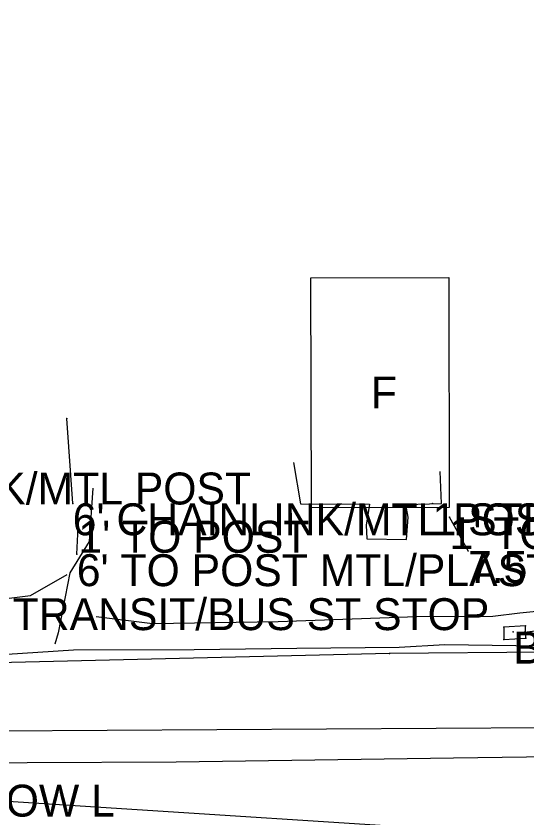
# Model space of a CAD drawing. Extents: x 1304270 to 1306561, y 1876019 to 1876752.
# Drawn here: x 1305816.1 to 1305896.1, y 1876400.4 to 1876526.1 of the extents above; entities that cross this region are included whole.
import ezdxf

# ---------------------------------------------------------------- set-up
doc = ezdxf.new("R2010")
doc.units = 0
for name, color, linetype in [('Default', 7, 'Continuous'), ('S_BUILDING', 7, 'Continuous'), ('S_BUILDING_ANNOT', 7, 'Continuous'), ('S_CROSS_DRAIN', 7, 'Continuous'), ('S_DRG_PT_SYM', 7, 'Continuous'), ('S_DROP_INLET', 7, 'Continuous'), ('S_EDGE_PAVEMENT', 7, 'Continuous'), ('S_ELECTRIC_UTILITIES_ANNOT', 7, 'Continuous'), ('S_FENCE', 7, 'Continuous'), ('S_FENCE_ANNOT', 7, 'Continuous'), ('S_MANHOLE_ANNOT', 7, 'Continuous'), ('S_MISC_STRUCTURES_ANNOT', 7, 'Continuous'), ('S_MSC_PT_SYM', 7, 'Continuous'), ('S_PARKING', 7, 'Continuous'), ('S_PAVEMENT_CROWN', 7, 'Continuous'), ('S_SANITARY_SEWER', 7, 'Continuous'), ('S_SHOULDER', 7, 'Continuous'), ('S_SIGN', 7, 'Continuous'), ('S_SIGN_ANNOT', 7, 'Continuous'), ('S_STR_PT_SYM', 7, 'Continuous'), ('S_UTL_PT_SYM', 7, 'Continuous'), ('S_WATER_UTILITIES', 7, 'Continuous')]:
    doc.layers.add(name, color=color, linetype=linetype)

msp = doc.modelspace()

# ---------------------------------------------------------------- linework, layer by layer
at = {"layer": 'Default'}
msp.add_line((1305473.53, 1876424.94), (1305993.25, 1876391.55), dxfattribs=at)
at = {"layer": 'S_BUILDING'}
msp.add_lwpolyline([(1305883.85, 1876485.1), (1305883.93, 1876449.06), (1305862.33, 1876449.01), (1305862.25, 1876485.05)], close=True, dxfattribs=at)
at = {"layer": 'S_CROSS_DRAIN'}
msp.add_line((1305895.71, 1876429.5), (1305904.32, 1876430.63), dxfattribs=at)
at = {"layer": 'S_DRG_PT_SYM'}
for points in [[(1305892.49, 1876430.27), (1305892.49, 1876430.32), (1305892.49, 1876430.27), (1305892.44, 1876430.27), (1305892.49, 1876430.27), (1305892.49, 1876430.22), (1305892.49, 1876430.27), (1305892.54, 1876430.27)], [(1305895.71, 1876429.5), (1305895.71, 1876429.55), (1305895.71, 1876429.5), (1305895.66, 1876429.5), (1305895.71, 1876429.5), (1305895.71, 1876429.45), (1305895.71, 1876429.5), (1305895.76, 1876429.5)], [(1305895.85, 1876430.5), (1305895.85, 1876430.55), (1305895.85, 1876430.5), (1305895.8, 1876430.5), (1305895.85, 1876430.5), (1305895.85, 1876430.45), (1305895.85, 1876430.5), (1305895.9, 1876430.5)], [(1305892.45, 1876428.38), (1305892.45, 1876428.43), (1305892.45, 1876428.38), (1305892.4, 1876428.38), (1305892.45, 1876428.38), (1305892.45, 1876428.33), (1305892.45, 1876428.38), (1305892.5, 1876428.38)], [(1305895.93, 1876428.55), (1305895.93, 1876428.6), (1305895.93, 1876428.55), (1305895.88, 1876428.55), (1305895.93, 1876428.55), (1305895.93, 1876428.5), (1305895.93, 1876428.55), (1305895.98, 1876428.55)]]:
    msp.add_lwpolyline(points, dxfattribs=at)
at = {"layer": 'S_DROP_INLET'}
for p, q in [((1305892.49, 1876430.27), (1305892.45, 1876428.38)), ((1305895.85, 1876430.5), (1305892.49, 1876430.27)), ((1305895.93, 1876428.55), (1305895.85, 1876430.5)), ((1305892.45, 1876428.38), (1305895.93, 1876428.55))]:
    msp.add_line(p, q, dxfattribs=at)
at = {"layer": 'S_EDGE_PAVEMENT'}
msp.add_lwpolyline([(1305650.55, 1876423.21), (1305674.32, 1876423.35), (1305698.09, 1876423.48), (1305721.97, 1876423.8), (1305745.85, 1876424.12), (1305770.29, 1876424.67), (1305794.74, 1876425.23), (1305811.42, 1876425.85), (1305825.07, 1876426.72), (1305843.96, 1876426.78), (1305860.03, 1876426.98), (1305876.09, 1876427.18), (1305883.24, 1876427.59), (1305898.06, 1876427.36), (1305904.05, 1876427.05), (1305918.23, 1876426.76), (1305933.32, 1876426.78)], dxfattribs=at)
at = {"layer": 'S_FENCE'}
msp.add_line((1305824.93, 1876449.69), (1305824, 1876463.01), dxfattribs=at)
msp.add_lwpolyline([(1305824.93, 1876449.69), (1305824, 1876463.01)], dxfattribs=at)
msp.add_lwpolyline([(1305824.93, 1876449.69), (1305824, 1876463.01)], dxfattribs=at)
at = {"layer": 'S_MSC_PT_SYM'}
for points in [[(1305824, 1876463.01), (1305824, 1876463.06), (1305824, 1876463.01), (1305823.95, 1876463.01), (1305824, 1876463.01), (1305824, 1876462.96), (1305824, 1876463.01), (1305824.05, 1876463.01)], [(1305824.93, 1876449.69), (1305824.93, 1876449.74), (1305824.93, 1876449.69), (1305824.88, 1876449.69), (1305824.93, 1876449.69), (1305824.93, 1876449.64), (1305824.93, 1876449.69), (1305824.98, 1876449.69)], [(1305883.97, 1876447.52), (1305883.97, 1876447.57), (1305883.97, 1876447.52), (1305883.92, 1876447.52), (1305883.97, 1876447.52), (1305883.97, 1876447.47), (1305883.97, 1876447.52), (1305884.02, 1876447.52)], [(1305825.82, 1876446.96), (1305825.82, 1876447.01), (1305825.82, 1876446.96), (1305825.77, 1876446.96), (1305825.82, 1876446.96), (1305825.82, 1876446.91), (1305825.82, 1876446.96), (1305825.87, 1876446.96)], [(1305886.87, 1876442.23), (1305886.87, 1876442.28), (1305886.87, 1876442.23), (1305886.82, 1876442.23), (1305886.87, 1876442.23), (1305886.87, 1876442.18), (1305886.87, 1876442.23), (1305886.92, 1876442.23)], [(1305825.57, 1876441.72), (1305825.57, 1876441.77), (1305825.57, 1876441.72), (1305825.52, 1876441.72), (1305825.57, 1876441.72), (1305825.57, 1876441.67), (1305825.57, 1876441.72), (1305825.62, 1876441.72)]]:
    msp.add_lwpolyline(points, dxfattribs=at)
at = {"layer": 'S_PARKING'}
for points in [[(1305901.16, 1876526.05), (1305901.3, 1876519.98), (1305901.45, 1876495.85), (1305901.48, 1876479.31), (1305901.6, 1876457.42), (1305900.96, 1876445.11), (1305900.93, 1876443.49), (1305900.91, 1876441.84), (1305902.67, 1876441.64), (1305902.25, 1876438.69), (1305899.45, 1876436.19), (1305899.74, 1876432.97), (1305894.96, 1876432.47), (1305890.73, 1876431.98), (1305878.86, 1876431.91), (1305857.12, 1876431.13), (1305837.44, 1876430.83), (1305828.63, 1876431.93)], [(1305859.5, 1876456.1), (1305860.61, 1876449.63), (1305871.42, 1876449.58), (1305870.93, 1876446.28), (1305871.01, 1876444.12), (1305877.25, 1876444.05), (1305877.49, 1876447.51), (1305877.1, 1876449.51), (1305882.69, 1876449.69), (1305882.5, 1876454.71)], [(1305828.08, 1876452.09), (1305827.53, 1876443.73), (1305824.49, 1876438.81), (1305822.67, 1876429.41), (1305822.15, 1876427.63)]]:
    msp.add_lwpolyline(points, dxfattribs=at)
at = {"layer": 'S_PAVEMENT_CROWN'}
msp.add_lwpolyline([(1305794.47, 1876408.96), (1305817.8, 1876409.07), (1305841.14, 1876409.19), (1305862.85, 1876409.5), (1305884.57, 1876409.8), (1305899.82, 1876410.02), (1305912.34, 1876409.75), (1305924.85, 1876409.48), (1305937.98, 1876409.78), (1305951.12, 1876410.08), (1305965.04, 1876410.39), (1305978.96, 1876410.71), (1306003.9, 1876411.1), (1306028.84, 1876411.5), (1306053.64, 1876411.74), (1306078.45, 1876411.98)], dxfattribs=at)
at = {"layer": 'S_SANITARY_SEWER'}
msp.add_line((1305931.77, 1876414.75), (1305628.57, 1876412.86), dxfattribs=at)
at = {"layer": 'S_SHOULDER'}
msp.add_lwpolyline([(1305731.36, 1876429.4), (1305755.14, 1876430.48), (1305774.63, 1876431.35), (1305794.11, 1876432.21), (1305818.31, 1876435.26), (1305824.04, 1876438.54)], dxfattribs=at)
at = {"layer": 'S_SIGN'}
for p, q in [((1305886.87, 1876442.23), (1305883.97, 1876447.52)), ((1305825.57, 1876441.72), (1305825.82, 1876446.96))]:
    msp.add_line(p, q, dxfattribs=at)
at = {"layer": 'S_STR_PT_SYM'}
msp.add_lwpolyline([(1305881.31, 1876449.69), (1305881.31, 1876449.74), (1305881.31, 1876449.69), (1305881.26, 1876449.69), (1305881.31, 1876449.69), (1305881.31, 1876449.64), (1305881.31, 1876449.69), (1305881.36, 1876449.69)], dxfattribs=at)
at = {"layer": 'S_UTL_PT_SYM'}
for points in [[(1305893.95, 1876429.58), (1305893.95, 1876429.63), (1305893.95, 1876429.58), (1305893.9, 1876429.58), (1305893.95, 1876429.58), (1305893.95, 1876429.53), (1305893.95, 1876429.58), (1305894, 1876429.58)], [(1305874.58, 1876426.18), (1305874.58, 1876426.23), (1305874.58, 1876426.18), (1305874.53, 1876426.18), (1305874.58, 1876426.18), (1305874.58, 1876426.13), (1305874.58, 1876426.18), (1305874.63, 1876426.18)]]:
    msp.add_lwpolyline(points, dxfattribs=at)
at = {"layer": 'S_WATER_UTILITIES'}
for p, q in [((1305874.58, 1876426.18), (1305772.85, 1876423.7)), ((1305948.37, 1876426.7), (1305874.58, 1876426.18))]:
    msp.add_line(p, q, dxfattribs=at)

# ---------------------------------------------------------------- texts
at = {"layer": 'S_BUILDING_ANNOT'}
for s, p in [('F', (1305871.65, 1876464.56)), ('1 STRY WOOD AURTHURS BBQ/ABANDO', (1305881.31, 1876444.69))]:
    msp.add_text(s, height=5, dxfattribs=at).set_placement(p)
at = {"layer": 'S_ELECTRIC_UTILITIES_ANNOT'}
msp.add_text('POINT ON ROAD UNDER LOW L', height=5, dxfattribs=at).set_placement((1305729.74, 1876400.61))
at = {"layer": 'S_FENCE_ANNOT'}
for s, p in [("4' CHAINLINK/MTL POST", (1305775.05, 1876449.52)), ("6' CHAINLINK/MTL POST DECORATIV", (1305824.93, 1876444.69))]:
    msp.add_text(s, height=5, dxfattribs=at).set_placement(p)
at = {"layer": 'S_MANHOLE_ANNOT'}
msp.add_text('BOTTOM OF DI', height=5, dxfattribs=at).set_placement((1305893.95, 1876424.58))
at = {"layer": 'S_MISC_STRUCTURES_ANNOT'}
msp.add_text('PINE BLUFF TRANSIT/BUS ST STOP', height=5, dxfattribs=at).set_placement((1305775.03, 1876429.83))
at = {"layer": 'S_SIGN_ANNOT'}
for s, p in [("1' TO POST", (1305825.82, 1876441.96)), ("1' TO POST", (1305883.97, 1876442.52)), ('7.5 TO POST PLAST/LITE AURTHURS BBQ', (1305886.87, 1876437.23)), ("6' TO POST MTL/PLAST/LITE AUTHURS BBQ", (1305825.57, 1876436.72))]:
    msp.add_text(s, height=5, dxfattribs=at).set_placement(p)

doc.saveas('drawing.dxf')
